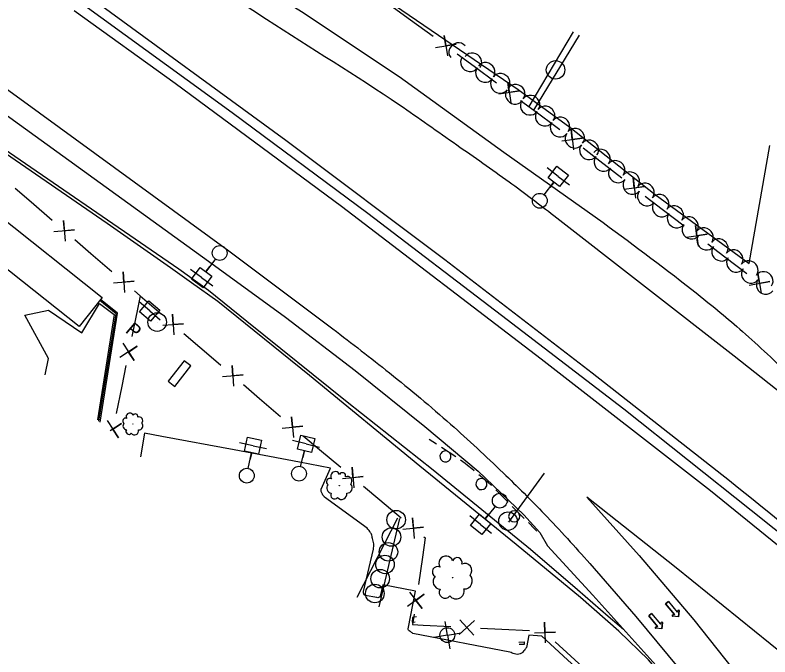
# Model space of a CAD drawing. Extents: x 1746010 to 1754829, y 655801 to 663091.
# Drawn here: x 1748004.9 to 1748412.4, y 661557 to 661903.4 of the extents above; entities that cross this region are included whole.
import ezdxf

# ---------------------------------------------------------------- set-up
doc = ezdxf.new("R2010")
doc.units = 0
for name, color, linetype in [('SURVEY - AERIAL SURVEY - Photo Control - Points - Elevations', 7, 'Continuous'), ('SURVEY - AERIAL SURVEY - Photo Control - Points - Locators', 7, 'Continuous'), ('SURVEY - AERIAL SURVEY - Photo Control - Points - Numbers', 7, 'Continuous'), ('SURVEY - AERIAL SURVEY - Photo Control with Text', 7, 'Continuous'), ('SURVEY - CENTERLINE - Existing Roads - Development', 7, 'Continuous'), ('SURVEY - CENTERLINE - Existing Roads Curve Text', 7, 'Continuous'), ('SURVEY - CENTERLINE - Existing Roads Text', 7, 'Continuous'), ('SURVEY - CENTERLINE - Preliminary Curve Text', 7, 'Continuous'), ('SURVEY - DRAINAGE - Area Shapes - Points - Elevations', 7, 'Continuous')]:
    doc.layers.add(name, color=color, linetype=linetype)

msp = doc.modelspace()

# ---------------------------------------------------------------- linework, layer by layer
at = {"layer": 'SURVEY - AERIAL SURVEY - Photo Control - Points - Elevations'}
for points in [[(1747986.63, 661839.49), (1748093.21, 661766.44), (1748109.37, 661754.82), (1748129.98, 661738.16), (1748184.08, 661694.65), (1748230.64, 661657.93), (1748283.12, 661615.05), (1748308.54, 661593.4), (1748325.1, 661578.87), (1748333.43, 661571.88)], [(1748455.36, 661428.68), (1748453.76, 661427.93), (1748418.75, 661469.48), (1748381.18, 661514.83), (1748359.32, 661540.99), (1748346.82, 661555.3), (1748330.8, 661570.77), (1748310.09, 661588.94), (1748275.38, 661617.6), (1748223.42, 661659.92), (1748163.78, 661708.77), (1748114.34, 661748.74), (1748100.11, 661758.93), (1748088.68, 661766.99), (1748054.59, 661790.9), (1747985.72, 661838.14)], [(1748221.68, 661578.51), (1748219.49, 661578.15), (1748219.23, 661575.68), (1748220.79, 661575.83)], [(1748276.78, 661564.85), (1748279.79, 661565.04), (1748279.65, 661563.61), (1748277.04, 661563.58)]]:
    msp.add_lwpolyline(points, dxfattribs=at)
at = {"layer": 'SURVEY - AERIAL SURVEY - Photo Control - Points - Locators'}
for points in [[(1747449.54, 662244.42), (1747495.25, 662212.96), (1747544.44, 662177.78), (1747597.81, 662139.99), (1747646.37, 662106.97), (1747700.87, 662070.9), (1747757.2, 662033.9), (1747810.92, 661997.83), (1747873.88, 661953.8), (1747937.26, 661909.07), (1748007.34, 661858.36)], [(1748255.32, 661961.61), (1748211.49, 661966.22), (1748205.36, 661964.35), (1748197.8, 661956.64), (1748196.77, 661954), (1748201.83, 661914.35), (1748276.47, 661863.25), (1748304.31, 661842.91), (1748350.44, 661806.58), (1748401.27, 661769.27), (1748412.36, 661832.91)], [(1748066.45, 661959.99), (1748109.91, 661930.15), (1748120.64, 661926.51), (1748137.02, 661919.36), (1748159.55, 661905.27), (1748212.25, 661870.14), (1748268.84, 661829.36), (1748322.43, 661791.33)], [(1748045.01, 661913.44), (1748151.1, 661835.82), (1748236.85, 661771.36), (1748316.51, 661710.36), (1748390.54, 661652.24)], [(1749014.37, 661130.26), (1748990.7, 661149.54), (1748916.31, 661209.97), (1748835.38, 661275.76), (1748731.71, 661360.72), (1748655.6, 661422.38), (1748555.07, 661504.4), (1748459.33, 661582.61), (1748380.29, 661646.59), (1748288.83, 661717.68), (1748181.12, 661800.02), (1748091.36, 661866.45), (1748036.84, 661905.72)], [(1748007.34, 661858.36), (1748120.21, 661776.06), (1748176.42, 661734.03)], [(1747998.74, 661850.34), (1748114.44, 661766.85), (1748150.82, 661740.26), (1748188.55, 661711.48), (1748226.16, 661681.35), (1748254.91, 661657.26), (1748279.52, 661633.58), (1748288.24, 661624.16), (1748292.36, 661616.95), (1748316.87, 661590.23), (1748360.58, 661541.79), (1748387.38, 661510.13), (1748454.99, 661429.3), (1748473.47, 661398.05), (1748494.32, 661368.3), (1748531.64, 661318.39), (1748548.98, 661297.94), (1748557.16, 661290.79)], [(1748569.65, 661577.83), (1748519.45, 661618.34), (1748437.79, 661684), (1748393.16, 661719.18), (1748295.79, 661794.96)], [(1748170.09, 661647.52), (1748175.15, 661658.78), (1748158.47, 661662.11), (1748123.11, 661668.76), (1748084.09, 661675.98), (1748074.68, 661677.68), (1748072.52, 661664.86)], [(1748195, 661626.4), (1748171.97, 661643.08)], [(1749004.96, 661081.96), (1748990.07, 661094.14), (1748934.34, 661138.81), (1748865.88, 661194.6), (1748789.64, 661256.64), (1748729.69, 661305.4), (1748673.84, 661351.11), (1748595.91, 661414.43), (1748530.55, 661467.92), (1748473.83, 661514.17), (1748421, 661557.21), (1748361.81, 661604.95), (1748313.62, 661643.08), (1748341.85, 661611.66), (1748371.26, 661577.05), (1748408.51, 661529.92)], [(1748192.97, 661592.33), (1748198.35, 661615.13)], [(1748315.21, 661607.38), (1748340.11, 661578.77), (1748380.23, 661530.42), (1748412.39, 661490.91)], [(1748217.16, 661572.15), (1748221.05, 661592.36), (1748203.34, 661595.88), (1748201.92, 661589.82)], [(1748200.16, 661589.04), (1748193.95, 661590.1)], [(1748272.02, 661559.54), (1748219.6, 661569.62)], [(1748316.93, 661542.65), (1748289.25, 661568.15), (1748282.18, 661568.77), (1748280.91, 661562.06)]]:
    msp.add_lwpolyline(points, dxfattribs=at)
for points in [[(1748295.79, 661794.96), (1748271.58, 661813.25), (1748243.3, 661833.2), (1748212.42, 661854.75), (1748140.62, 661900.99), (1748101.4, 661927.2)], [(1748322.43, 661791.33), (1748373.47, 661752.68), (1748397.57, 661732.62), (1748424.19, 661707.83), (1748446.67, 661685.36)], [(1748176.42, 661734.03), (1748206.99, 661710.24), (1748240.04, 661682.51), (1748268.39, 661656.26), (1748290.69, 661634.05), (1748315.21, 661607.38)], [(1748390.54, 661652.24), (1748458.5, 661597.34), (1748523.79, 661544.26)], [(1748171.97, 661643.08), (1748170.78, 661644.73), (1748170.21, 661646.2), (1748170.09, 661647.52)], [(1748198.35, 661615.13), (1748198.54, 661618.07), (1748197.88, 661620.82), (1748197.24, 661623.13), (1748196.34, 661624.67), (1748195, 661626.4)], [(1748193.95, 661590.1), (1748193.42, 661590.49), (1748193.05, 661591.45), (1748192.97, 661592.33)], [(1748201.92, 661589.82), (1748201.16, 661588.93), (1748200.16, 661589.04)], [(1748219.6, 661569.62), (1748218.18, 661570.69), (1748217.27, 661571.39), (1748217.16, 661572.15)], [(1748280.91, 661562.06), (1748279.83, 661560.5), (1748278.98, 661559.47), (1748277.62, 661558.62), (1748276.17, 661558.31), (1748274.48, 661558.53), (1748272.02, 661559.54)]]:
    msp.add_spline(points, degree=3, dxfattribs=at)
at = {"layer": 'SURVEY - AERIAL SURVEY - Photo Control - Points - Numbers'}
for points in [[(1748040.01, 661910.33), (1748122.02, 661850.78), (1748195.38, 661796.53), (1748267.56, 661741.32), (1748333.52, 661690.82), (1748402.34, 661636.08), (1748451.04, 661597.23), (1748504.04, 661553.85), (1748559.78, 661508.8), (1748636.39, 661445.77), (1748709.27, 661386.44), (1748757.29, 661347.34), (1748822.35, 661294.7), (1748882.58, 661246), (1748955.33, 661186.03), (1749015.15, 661137.9)], [(1748050.8, 661683.6), (1748060.21, 661742.4), (1748051.01, 661749.86)], [(1748050.16, 661684.16), (1748059.43, 661742.1), (1748050.56, 661749.3)], [(1748228.37, 661674.41), (1748232.32, 661671.87)], [(1748235.02, 661670.14), (1748242.76, 661665.17)], [(1748245.37, 661663.33), (1748247.79, 661661.5), (1748249.11, 661660.47)], [(1748249.11, 661660.47), (1748251.55, 661658.57), (1748252.76, 661657.53)], [(1748255.19, 661655.44), (1748257, 661653.9), (1748262.1, 661649.38)], [(1748264.37, 661647.13), (1748267.69, 661643.8)], [(1748267.69, 661643.8), (1748271.01, 661640.47)], [(1748273.27, 661638.2), (1748279.76, 661631.68)], [(1748282.02, 661629.41), (1748285.33, 661626.08)], [(1748285.33, 661626.08), (1748286.64, 661624.78)]]:
    msp.add_lwpolyline(points, dxfattribs=at)
for centre, start, end in [((1748237.23, 661665.16), 170.5534, 170.5394), ((1748256.64, 661650.21), 161.7738, 161.7598), ((1748274.36, 661632.86), 158.1458, 158.1318)]:
    msp.add_arc(centre, 3, start, end, dxfattribs=at)
at = {"layer": 'SURVEY - AERIAL SURVEY - Photo Control with Text'}
for p, q in [((1748306.16, 661894.28), (1748282.25, 661853.97)), ((1748284.94, 661852.01), (1748309.54, 661892.54)), ((1748296.67, 661873.81), (1748296.67, 661873.81)), ((1748271.39, 661629.74), (1748290.7, 661656.19)), ((1748189.55, 661589.16), (1748211.48, 661632.05)), ((1748212.4, 661631.61), (1748201.25, 661583.93)), ((1748210.62, 661630.95), (1748210.62, 661630.95)), ((1748270.99, 661630.22), (1748270.99, 661630.22)), ((1748208.05, 661621.64), (1748208.05, 661621.64)), ((1748206.45, 661613.6), (1748206.45, 661613.6)), ((1748204.58, 661606.82), (1748204.58, 661606.82)), ((1748201.95, 661599.17), (1748201.95, 661599.17)), ((1748199.12, 661591.13), (1748199.12, 661591.13))]:
    msp.add_line(p, q, dxfattribs=at)
msp.add_lwpolyline([(1748091.09, 661702.98), (1748099.68, 661714.03), (1748096.08, 661716.81), (1748087.5, 661705.75)], close=True, dxfattribs=at)
for centre in [(1748296.68, 661873.77), (1748210.61, 661630.99), (1748270.98, 661630.26), (1748208.09, 661621.65), (1748206.44, 661613.64), (1748204.57, 661606.85), (1748201.99, 661599.18), (1748199.11, 661591.17)]:
    msp.add_circle(centre, 5, dxfattribs=at)
at = {"layer": 'SURVEY - CENTERLINE - Existing Roads - Development'}
msp.add_line((1748081.56, 661737.63), (1748081.56, 661737.63), dxfattribs=at)
for points in [[(1748209.16, 661907.48), (1748218.38, 661900.79)], [(1748218.38, 661900.79), (1748230.52, 661891.98)], [(1748231.91, 661885.91), (1748243, 661887.73), (1748237.5, 661886.79), (1748236.61, 661892.37), (1748238.3, 661881.28)], [(1748243.52, 661882.49), (1748252.69, 661875.74)], [(1748252.69, 661875.74), (1748264.77, 661866.85)], [(1748266.12, 661860.77), (1748277.22, 661862.52), (1748271.71, 661861.61), (1748270.86, 661867.2), (1748272.48, 661856.09)], [(1748277.73, 661857.31), (1748286.91, 661850.56)], [(1748286.91, 661850.56), (1748296.06, 661843.82), (1748298.92, 661841.59)], [(1748300.1, 661835.47), (1748311.25, 661836.9), (1748305.71, 661836.16), (1748305.02, 661841.76), (1748306.32, 661830.61)], [(1748311.6, 661831.69), (1748320.59, 661824.68)], [(1748320.59, 661824.68), (1748332.41, 661815.45)], [(1748333.59, 661809.34), (1748344.74, 661810.77), (1748339.2, 661810.02), (1748338.51, 661815.63), (1748339.81, 661804.48)], [(1748004.92, 661809.92), (1748013.56, 661802.48)], [(1748345.11, 661805.57), (1748354.18, 661798.68)], [(1748013.56, 661802.48), (1748024.93, 661792.7)], [(1748354.18, 661798.68), (1748366.12, 661789.6)], [(1748025.82, 661786.53), (1748037.01, 661787.43), (1748031.45, 661786.95), (1748031.02, 661792.58), (1748031.81, 661781.38)], [(1748367.38, 661783.5), (1748378.51, 661785.07), (1748372.98, 661784.26), (1748372.22, 661789.85), (1748373.66, 661778.72)], [(1748037.13, 661782.2), (1748045.77, 661774.76)], [(1748378.93, 661779.86), (1748388, 661772.96)], [(1748045.77, 661774.76), (1748057.14, 661764.98)], [(1748388, 661772.96), (1748399.94, 661763.89)], [(1748058.04, 661758.81), (1748069.22, 661759.71), (1748063.66, 661759.23), (1748063.23, 661764.86), (1748064.02, 661753.66)], [(1748401.22, 661757.66), (1748412.31, 661759.51), (1748406.81, 661758.55), (1748405.92, 661764.12), (1748407.62, 661753.05)], [(1748069.34, 661754.48), (1748072.4, 661751.84), (1748070.93, 661744.64)], [(1748072.4, 661751.84), (1748083.75, 661742.07)], [(1748021.08, 661709.24), (1748022.91, 661718.07), (1748010.11, 661741.43), (1748022.88, 661744.08), (1748040.87, 661731.83), (1748050.36, 661747.7), (1748058.27, 661741.67), (1748049.39, 661684.82)], [(1748070.93, 661744.64), (1748067.94, 661729.97)], [(1748084.63, 661735.92), (1748095.83, 661736.8), (1748090.27, 661736.33), (1748089.86, 661741.95), (1748090.6, 661730.78)], [(1748095.93, 661731.58), (1748104.56, 661724.16)], [(1748062.99, 661726.2), (1748069.24, 661716.85), (1748066.11, 661721.48), (1748070.82, 661724.58), (1748061.42, 661718.47)], [(1748104.56, 661724.16), (1748111.9, 661717.84), (1748115.92, 661714.39)], [(1748064.73, 661714.21), (1748062.46, 661703.06)], [(1748116.82, 661708.23), (1748128.02, 661709.12), (1748122.46, 661708.64), (1748122.03, 661714.27), (1748122.81, 661703.08)], [(1748062.46, 661703.06), (1748059.46, 661688.39)], [(1748128.13, 661703.9), (1748136.78, 661696.47)], [(1748136.78, 661696.47), (1748148.16, 661686.7)], [(1748054.52, 661684.62), (1748060.77, 661675.27), (1748057.63, 661679.9), (1748062.34, 661683), (1748056.16, 661678.98)], [(1748149.08, 661680.47), (1748160.25, 661681.53), (1748154.7, 661680.96), (1748154.19, 661686.59), (1748155.14, 661675.4)], [(1748160.44, 661676.29), (1748169.18, 661668.98)], [(1748169.18, 661668.98), (1748180.69, 661659.35)], [(1748181.67, 661653.2), (1748192.84, 661654.25), (1748187.3, 661653.69), (1748186.79, 661659.32), (1748187.73, 661648.13)], [(1748193.03, 661649.02), (1748201.78, 661641.71)], [(1748201.78, 661641.71), (1748213.28, 661632.08)], [(1748214.27, 661625.93), (1748225.44, 661626.98), (1748219.89, 661626.42), (1748219.38, 661632.05), (1748220.32, 661620.86)], [(1748225.63, 661621.75), (1748226.29, 661621.2), (1748224.78, 661610.8)], [(1748224.78, 661610.8), (1748222.63, 661595.99)], [(1748217.9, 661591.93), (1748224.69, 661582.99), (1748221.29, 661587.41), (1748225.82, 661590.79), (1748216.77, 661584.13)], [(1748220.32, 661580.09), (1748219.5, 661574.43), (1748225.16, 661574.14)], [(1748244.61, 661569.02), (1748252.93, 661576.58), (1748248.82, 661572.8), (1748245.04, 661576.99), (1748252.5, 661568.61)], [(1748285.33, 661569.91), (1748296.56, 661570.39), (1748290.98, 661570.12), (1748290.77, 661575.76), (1748291.13, 661564.54)], [(1748225.16, 661574.14), (1748240.14, 661573.35)], [(1748256.21, 661572.51), (1748267.59, 661571.91)], [(1748267.59, 661571.91), (1748282.57, 661571.13)], [(1748296.48, 661565.16), (1748304.84, 661557.41)], [(1748304.84, 661557.41), (1748315.84, 661547.21)]]:
    msp.add_lwpolyline(points, dxfattribs=at)
msp.add_lwpolyline([(1747994.36, 661796.61), (1748051.89, 661750.98), (1748039.38, 661735.2), (1747971.11, 661789.35), (1747981.69, 661802.69), (1747992.43, 661794.18)], close=True, dxfattribs=at)
msp.add_circle((1748081.57, 661737.67), 5, dxfattribs=at)
at = {"layer": 'SURVEY - CENTERLINE - Existing Roads Curve Text'}
for p, q in [((1748298.14, 661816.29), (1748292.17, 661820.83)), ((1748298.14, 661816.29), (1748304.12, 661811.75)), ((1748290.52, 661806.26), (1748295.78, 661813.18)), ((1748295.54, 661812.86), (1748293.6, 661810.32)), ((1748113.02, 661771.81), (1748107.86, 661764.8)), ((1748105.55, 661761.66), (1748099.51, 661766.11)), ((1748108.1, 661765.13), (1748110, 661767.7)), ((1748105.55, 661761.66), (1748111.58, 661757.21)), ((1748077.53, 661743.71), (1748071.81, 661748.57)), ((1748077.53, 661743.71), (1748083.25, 661738.85)), ((1748133.33, 661670.96), (1748125.99, 661672.48)), ((1748161.96, 661671.94), (1748154.67, 661673.68)), ((1748133.33, 661670.96), (1748140.68, 661669.44)), ((1748161.96, 661671.94), (1748169.26, 661670.2)), ((1748130.77, 661658.62), (1748132.54, 661667.14)), ((1748132.46, 661666.75), (1748131.81, 661663.62)), ((1748159.04, 661659.68), (1748161.06, 661668.15)), ((1748160.96, 661667.76), (1748160.22, 661664.64)), ((1748264.13, 661638.22), (1748258.66, 661631.46)), ((1748256.21, 661628.42), (1748250.37, 661633.14)), ((1748258.91, 661631.77), (1748260.92, 661634.26)), ((1748256.21, 661628.42), (1748262.04, 661623.71))]:
    msp.add_line(p, q, dxfattribs=at)
for points in [[(1748303.61, 661817.04), (1748298.89, 661810.82), (1748292.68, 661815.54), (1748297.4, 661821.75)], [(1748100.09, 661760.84), (1748104.72, 661767.12), (1748111, 661762.49), (1748106.37, 661756.21)], [(1748077.08, 661749.21), (1748083.03, 661744.16), (1748077.98, 661738.21), (1748072.03, 661743.26)], [(1748166.66, 661674.83), (1748164.85, 661667.24), (1748157.26, 661669.05), (1748159.07, 661676.64)], [(1748137.95, 661673.99), (1748136.36, 661666.35), (1748128.72, 661667.93), (1748130.31, 661675.57)], [(1748250.72, 661627.84), (1748255.62, 661633.91), (1748261.69, 661629.01), (1748256.79, 661622.94)]]:
    msp.add_lwpolyline(points, close=True, dxfattribs=at)
for centre in [(1748288.16, 661803.15), (1748115.33, 661774.95), (1748129.98, 661654.8), (1748158.13, 661655.89), (1748266.58, 661641.26)]:
    msp.add_circle(centre, 4, dxfattribs=at)
at = {"layer": 'SURVEY - CENTERLINE - Existing Roads Text'}
for centre, radius in [((1748068.45, 661682.64), 0.0678), ((1748179.97, 661649.38), 0.0866), ((1748241.06, 661599.73), 0.133)]:
    msp.add_circle(centre, radius, dxfattribs=at)
for centre, radius, start, end in [((1748064.42, 661684.32), 1.47, 61.5727, 238.8919), ((1748066.76, 661686.66), 1.94, 18.9541, 212.3738), ((1748069.82, 661686.78), 1.33, 338.9334, 157.679), ((1748071.85, 661684.52), 1.94, 316.8172, 113.6061), ((1748065.18, 661681.63), 2.09, 136.8598, 263.7055), ((1748071.66, 661681.68), 2.21, 265.87, 43.3942), ((1748066.31, 661678.67), 1.62, 147.0187, 322.019), ((1748069.35, 661678.99), 2.2, 216.7658, 12.6043), ((1748177.74, 661654.48), 2.48, 19.6645, 213.0842), ((1748181.65, 661654.69), 1.7, 339.6438, 158.3894), ((1748174.79, 661651.46), 1.88, 62.2831, 239.6023), ((1748184.27, 661651.84), 2.48, 317.5276, 114.3165), ((1748175.8, 661648.04), 2.67, 137.5702, 264.4159), ((1748184.07, 661648.2), 2.83, 266.5804, 44.1046), ((1748177.3, 661644.27), 2.07, 147.7291, 322.7294), ((1748181.17, 661644.73), 2.81, 217.4762, 13.3147), ((1748237.54, 661607.55), 3.81, 20.2964, 213.7161), ((1748243.57, 661607.94), 2.62, 340.2758, 159.0214), ((1748247.65, 661603.59), 3.82, 318.1596, 114.9485), ((1748233.05, 661602.85), 2.9, 62.9151, 240.2343), ((1748234.68, 661597.59), 4.11, 138.2022, 265.0478), ((1748247.41, 661597.98), 4.35, 267.2123, 44.7366), ((1748237.04, 661591.82), 3.19, 148.3611, 323.3613), ((1748243, 661592.59), 4.33, 218.1082, 13.9467)]:
    msp.add_arc(centre, radius, start, end, dxfattribs=at)
for centre, major_axis in [((1748243.96, 661883.57), (3.89, 3.15)), ((1748250.32, 661877.72), (-4.08, 2.9)), ((1748251.95, 661878.11), (4.03, -2.97)), ((1748259.05, 661872.92), (4.04, -2.94)), ((1748258.4, 661871.86), (-4.04, 2.95)), ((1748267.14, 661867.04), (4.04, -2.94)), ((1748266.47, 661865.98), (-4.04, 2.95)), ((1748275.23, 661861.16), (4.04, -2.94)), ((1748274.54, 661860.09), (-4.04, 2.95)), ((1748283.31, 661855.28), (4.04, -2.94)), ((1748282.6, 661854.21), (-4.04, 2.95)), ((1748291.4, 661849.4), (4.04, -2.94)), ((1748290.65, 661848.28), (-4.02, 2.97)), ((1748299.48, 661843.52), (4.04, -2.94)), ((1748298.69, 661842.34), (-4.02, 2.97)), ((1748306.73, 661836.39), (-3.91, 3.12)), ((1748307.4, 661837.41), (3.85, -3.19)), ((1748315.1, 661831.04), (3.85, -3.19)), ((1748314.54, 661830.16), (-3.91, 3.12)), ((1748321.33, 661826.11), (3.96, -3.06)), ((1748322.35, 661823.92), (-3.91, 3.12)), ((1748329.24, 661820.01), (3.96, -3.06)), ((1748330.17, 661817.68), (-3.91, 3.12)), ((1748337.14, 661813.91), (3.96, -3.06)), ((1748337.98, 661811.45), (-3.91, 3.12)), ((1748345.04, 661807.81), (3.96, -3.06)), ((1748345.82, 661805.25), (-4.01, 2.99)), ((1748352.95, 661801.71), (3.96, -3.06)), ((1748353.84, 661799.28), (-4.01, 2.99)), ((1748360.87, 661795.63), (4.02, -2.97)), ((1748361.86, 661793.31), (-4.01, 2.99)), ((1748368.92, 661789.69), (4.02, -2.97)), ((1748369.88, 661787.34), (-4.01, 2.99)), ((1748376.96, 661783.75), (4.02, -2.97)), ((1748377.9, 661781.38), (-4.01, 2.99)), ((1748385, 661777.81), (4.02, -2.97)), ((1748385.92, 661775.41), (-4.01, 2.99)), ((1748393.05, 661771.87), (4.02, -2.97)), ((1748393.94, 661769.44), (-4.01, 2.99)), ((1748401.11, 661765.96), (4.05, -2.93)), ((1748401.96, 661763.47), (-4.01, 2.99)), ((1748409.22, 661760.09), (4.05, -2.93)), ((1748409.98, 661757.5), (-4.02, 2.97))]:
    msp.add_ellipse(centre, major_axis=major_axis, ratio=0.940188, start_param=0, end_param=3.141593, dxfattribs=at)
at = {"layer": 'SURVEY - CENTERLINE - Preliminary Curve Text'}
for q in [(1748237.05, 661576.1), (1748230.89, 661567.47), (1748245.68, 661569.94), (1748239.52, 661561.31)]:
    msp.add_line((1748238.28, 661568.7), q, dxfattribs=at)
msp.add_circle((1748238.28, 661568.7), 4, dxfattribs=at)
at = {"layer": 'SURVEY - DRAINAGE - Area Shapes - Points - Elevations'}
for p, q in [((1748356.11, 661585.56), (1748357.63, 661586.81)), ((1748357.63, 661586.81), (1748356.11, 661585.56)), ((1748357.63, 661586.81), (1748362.42, 661581.02)), ((1748357.63, 661586.81), (1748362.42, 661581.02)), ((1748360.91, 661579.77), (1748356.11, 661585.56)), ((1748356.11, 661585.56), (1748360.91, 661579.77)), ((1748347, 661579.11), (1748348.51, 661580.37)), ((1748348.51, 661580.37), (1748347, 661579.11)), ((1748351.8, 661573.32), (1748347, 661579.11)), ((1748347, 661579.11), (1748351.8, 661573.32)), ((1748348.51, 661580.37), (1748353.31, 661574.58)), ((1748348.51, 661580.37), (1748353.31, 661574.58)), ((1748359.73, 661579.4), (1748360.91, 661579.77)), ((1748360.91, 661579.77), (1748359.73, 661579.4)), ((1748363.15, 661578.61), (1748359.78, 661578.92)), ((1748363.15, 661578.61), (1748359.78, 661578.92)), ((1748362.42, 661581.02), (1748363, 661582.11)), ((1748362.42, 661581.02), (1748363, 661582.11)), ((1748363.46, 661581.97), (1748363.15, 661578.61)), ((1748363.15, 661578.61), (1748363.46, 661581.97)), ((1748353.31, 661574.58), (1748353.89, 661575.66)), ((1748353.31, 661574.58), (1748353.89, 661575.66)), ((1748354.35, 661575.53), (1748354.03, 661572.16)), ((1748354.03, 661572.16), (1748354.35, 661575.53)), ((1748350.62, 661572.96), (1748351.8, 661573.32)), ((1748351.8, 661573.32), (1748350.62, 661572.96)), ((1748354.03, 661572.16), (1748350.67, 661572.48)), ((1748354.03, 661572.16), (1748350.67, 661572.48))]:
    msp.add_line(p, q, dxfattribs=at)
for centre, start, end in [((1748359.81, 661579.17), 107.1878, 264.6361), ((1748359.81, 661579.17), 107.1878, 264.6361), ((1748363.22, 661581.99), 354.6361, 152.1292), ((1748363.22, 661581.99), 354.6361, 152.1292), ((1748354.1, 661575.55), 354.6361, 152.1292), ((1748354.1, 661575.55), 354.6361, 152.1292), ((1748350.69, 661572.72), 107.1878, 264.6361), ((1748350.69, 661572.72), 107.1878, 264.6361)]:
    msp.add_arc(centre, 0.246, start, end, dxfattribs=at)

# ---------------------------------------------------------------- texts
at = {"layer": 'SURVEY - CENTERLINE - Existing Roads Curve Text'}
msp.add_text('P', height=7.48, rotation=319.6529, dxfattribs=at).set_placement((1748063.97, 661732.53))

doc.saveas('drawing.dxf')
